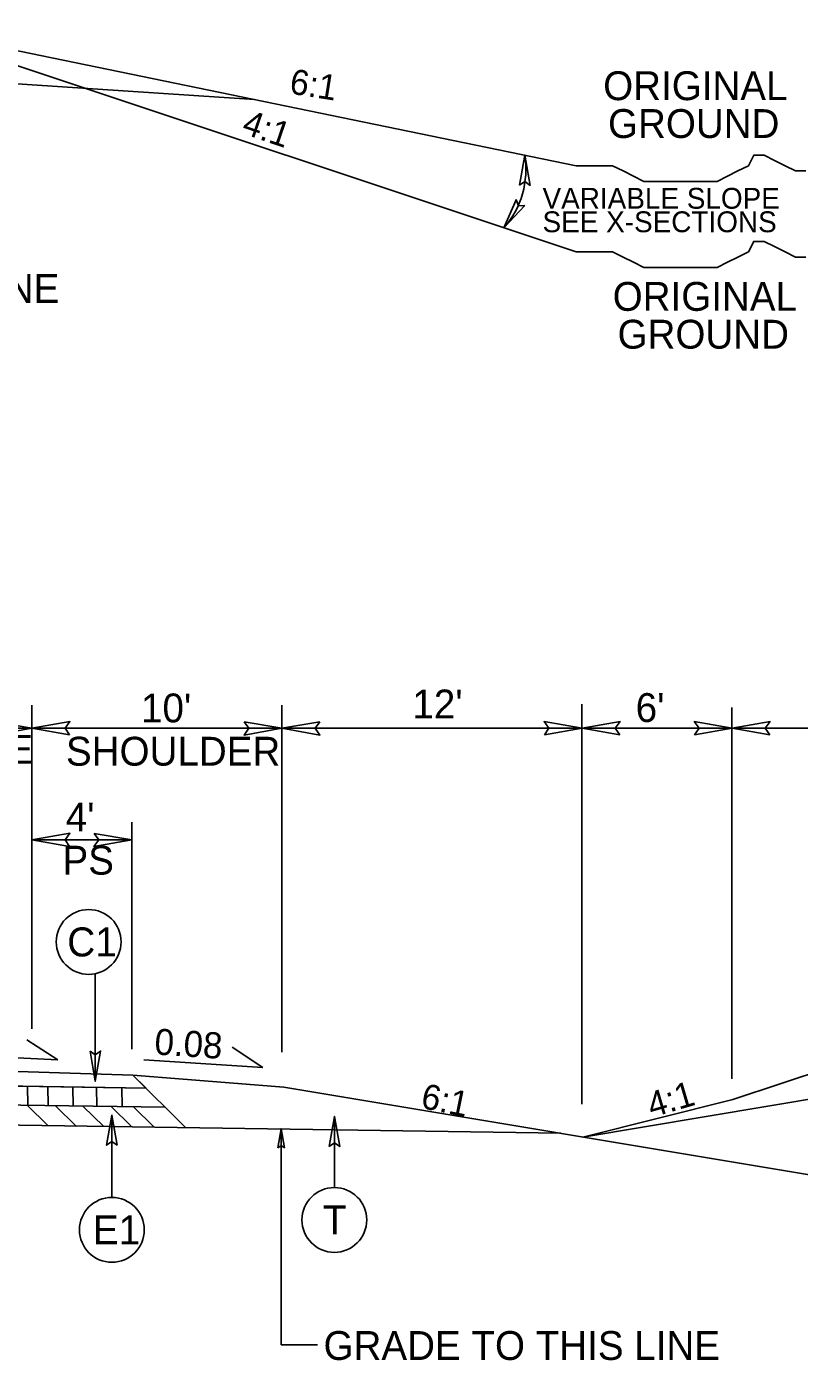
# Model space of a CAD drawing. Extents: x 2176024 to 2177225, y 75947 to 76635.
# Drawn here: x 2176346.9 to 2176377.8, y 76465.6 to 76518.9 of the extents above; entities that cross this region are included whole.
import ezdxf

# ---------------------------------------------------------------- set-up
doc = ezdxf.new("R2010")
doc.units = 0
for name, color, linetype in [('Old_Level_1', 7, 'Continuous'), ('Old_Level_11', 7, 'Continuous'), ('Prop Dimension', 7, 'Continuous'), ('Typical Curb CELL', 7, 'Continuous'), ('Typical Hinge Slope Arterial CELL', 7, 'Continuous'), ('Typical Pavement Slope CELL', 7, 'Continuous'), ('Typical Pavement Slope Information CELL', 7, 'Continuous'), ('Typical Shoulder Slope CELL', 7, 'Continuous'), ('Typical Slope Point Local CELL', 7, 'Continuous'), ('Typical Terminator CELL', 7, 'Continuous'), ('Typical Text General CELL', 7, 'Continuous')]:
    doc.layers.add(name, color=color, linetype=linetype)

msp = doc.modelspace()

# ---------------------------------------------------------------- linework, layer by layer
at = {"layer": 'Old_Level_1'}
for p, q in [((2176346.958, 76475.756), (2176346.947, 76476.512)), ((2176347.771, 76475.744), (2176347.76, 76476.5)), ((2176348.769, 76475.723), (2176348.758, 76476.485)), ((2176349.709, 76475.715), (2176349.698, 76476.471)), ((2176350.727, 76475.7), (2176350.716, 76476.456)), ((2176347.758, 76474.944), (2176346.931, 76475.754)), ((2176348.898, 76474.911), (2176348.063, 76475.73)), ((2176349.989, 76474.903), (2176349.153, 76475.721)), ((2176351.108, 76474.899), (2176350.272, 76475.717)), ((2176352.001, 76474.88), (2176351.174, 76475.69))]:
    msp.add_line(p, q, dxfattribs=at)
at = {"layer": 'Old_Level_11'}
for p, q in [((2176349.651, 76481.016), (2176349.651, 76476.714)), ((2176350.314, 76472.07), (2176350.314, 76475.365)), ((2176359.21, 76472.467), (2176359.21, 76475.309))]:
    msp.add_line(p, q, dxfattribs=at)
for points in [[(2176366.616, 76512.535), (2176366.823, 76513.735), (2176367.036, 76512.528), (2176366.823, 76512.682)], [(2176366.826, 76511.719), (2176365.99, 76510.833), (2176366.479, 76511.957), (2176366.572, 76511.711)], [(2176349.444, 76477.914), (2176349.651, 76476.714), (2176349.864, 76477.92), (2176349.651, 76477.767)], [(2176350.521, 76474.165), (2176350.314, 76475.365), (2176350.101, 76474.159), (2176350.314, 76474.312)], [(2176359.003, 76474.109), (2176359.21, 76475.309), (2176359.423, 76474.103), (2176359.21, 76474.256)]]:
    msp.add_lwpolyline(points, close=True, dxfattribs=at)
for centre in [(2176349.386, 76482.285), (2176359.21, 76471.171), (2176350.314, 76470.774)]:
    msp.add_circle(centre, 1.296, dxfattribs=at)
at = {"layer": 'Prop Dimension'}
for p, q in [((2176347.116, 76478.812), (2176347.116, 76491.752)), ((2176357.116, 76477.884), (2176357.116, 76491.752)), ((2176369.103, 76475.797), (2176369.103, 76491.79)), ((2176375.103, 76476.815), (2176375.103, 76491.656)), ((2176347.116, 76490.824), (2176335.116, 76490.824)), ((2176357.116, 76490.824), (2176347.116, 76490.824)), ((2176357.116, 76490.824), (2176369.116, 76490.824)), ((2176369.116, 76490.824), (2176375.116, 76490.824)), ((2176375.116, 76490.824), (2176385.116, 76490.824)), ((2176351.116, 76477.998), (2176351.116, 76487.074)), ((2176351.116, 76486.364), (2176347.116, 76486.364)), ((2176357.077, 76474.814), (2176357.077, 76466.179)), ((2176358.531, 76466.179), (2176357.077, 76466.179))]:
    msp.add_line(p, q, dxfattribs=at)
at = {"layer": 'Typical Curb CELL'}
msp.add_line((2176368.26, 76474.633), (2176343.298, 76475.004), dxfattribs=at)
at = {"layer": 'Typical Hinge Slope Arterial CELL'}
msp.add_arc((2176363.337, 76513.166), 3.532, 318.6696, 9.272, dxfattribs=at)
at = {"layer": 'Typical Pavement Slope CELL'}
for p, q in [((2176368.874, 76513.313), (2176341.866, 76518.875)), ((2176329.886, 76517.675), (2176356.018, 76515.96)), ((2176369.145, 76474.486), (2176385.145, 76477.152)), ((2176351.157, 76476.96), (2176353.274, 76474.856)), ((2176343.298, 76476.566), (2176351.679, 76476.441)), ((2176385.145, 76471.819), (2176357.193, 76476.478)), ((2176343.298, 76475.811), (2176352.451, 76475.675))]:
    msp.add_line(p, q, dxfattribs=at)
at = {"layer": 'Typical Pavement Slope Information CELL'}
for p, q in [((2176348.153, 76477.572), (2176346.912, 76478.368)), ((2176348.153, 76477.572), (2176340.654, 76477.922)), ((2176356.344, 76477.262), (2176355.119, 76478.082)), ((2176356.344, 76477.262), (2176351.598, 76477.576))]:
    msp.add_line(p, q, dxfattribs=at)
at = {"layer": 'Typical Shoulder Slope CELL'}
for p, q in [((2176368.874, 76509.872), (2176341.866, 76518.875)), ((2176375.145, 76475.986), (2176385.145, 76479.319)), ((2176351.157, 76476.96), (2176357.193, 76476.478)), ((2176369.145, 76474.486), (2176375.145, 76475.986))]:
    msp.add_line(p, q, dxfattribs=at)
at = {"layer": 'Typical Slope Point Local CELL'}
for p, q in [((2176326.441, 76477.731), (2176351.157, 76476.96)), ((2176351.157, 76476.96), (2176343.298, 76477.206)), ((2176351.679, 76476.441), (2176351.157, 76476.96))]:
    msp.add_line(p, q, dxfattribs=at)
for points in [[(2176378.064, 76513.105), (2176377.646, 76513.105), (2176377.229, 76513.313), (2176376.811, 76513.522), (2176376.393, 76513.732), (2176375.976, 76513.732), (2176375.766, 76513.313), (2176375.348, 76513.105), (2176374.931, 76512.895), (2176374.513, 76512.687), (2176374.095, 76512.687), (2176373.678, 76512.687), (2176373.26, 76512.687), (2176372.842, 76512.687), (2176372.425, 76512.687), (2176372.007, 76512.687), (2176371.59, 76512.687), (2176371.172, 76512.895), (2176370.754, 76513.105), (2176370.337, 76513.313), (2176369.709, 76513.313), (2176369.292, 76513.313), (2176368.874, 76513.313)], [(2176378.064, 76509.664), (2176377.646, 76509.664), (2176377.229, 76509.872), (2176376.811, 76510.082), (2176376.393, 76510.291), (2176375.976, 76510.291), (2176375.766, 76509.872), (2176375.348, 76509.664), (2176374.931, 76509.454), (2176374.513, 76509.246), (2176374.095, 76509.246), (2176373.678, 76509.246), (2176373.26, 76509.246), (2176372.842, 76509.246), (2176372.425, 76509.246), (2176372.007, 76509.246), (2176371.59, 76509.246), (2176371.172, 76509.454), (2176370.754, 76509.664), (2176370.337, 76509.872), (2176369.709, 76509.872), (2176369.292, 76509.872), (2176368.874, 76509.872)], [(2176343.298, 76476.566), (2176343.991, 76476.556), (2176344.988, 76476.541), (2176345.929, 76476.527), (2176351.679, 76476.441)]]:
    msp.add_lwpolyline(points, dxfattribs=at)
at = {"layer": 'Typical Terminator CELL'}
for points in [[(2176345.606, 76491.084), (2176347.116, 76490.824), (2176345.598, 76490.556), (2176345.791, 76490.824)], [(2176348.626, 76490.564), (2176347.116, 76490.824), (2176348.634, 76491.093), (2176348.441, 76490.824)], [(2176355.606, 76491.084), (2176357.116, 76490.824), (2176355.598, 76490.556), (2176355.791, 76490.824)], [(2176358.626, 76491.084), (2176357.116, 76490.824), (2176358.634, 76490.556), (2176358.441, 76490.824)], [(2176367.606, 76490.564), (2176369.116, 76490.824), (2176367.598, 76491.093), (2176367.791, 76490.824)], [(2176370.626, 76490.564), (2176369.116, 76490.824), (2176370.634, 76491.093), (2176370.441, 76490.824)], [(2176373.606, 76490.564), (2176375.116, 76490.824), (2176373.598, 76491.093), (2176373.791, 76490.824)], [(2176376.626, 76490.564), (2176375.116, 76490.824), (2176376.634, 76491.093), (2176376.441, 76490.824)], [(2176348.626, 76486.104), (2176347.116, 76486.364), (2176348.634, 76486.632), (2176348.441, 76486.364)], [(2176349.606, 76486.624), (2176351.116, 76486.364), (2176349.598, 76486.096), (2176349.791, 76486.364)], [(2176356.947, 76474.059), (2176357.077, 76474.814), (2176357.211, 76474.055), (2176357.077, 76474.152)]]:
    msp.add_lwpolyline(points, close=True, dxfattribs=at)

# ---------------------------------------------------------------- texts
at = {"layer": 'Old_Level_11'}
for s, p in [('C1', (2176348.529, 76481.705)), ('E1', (2176349.55, 76470.194)), ('T', (2176358.753, 76470.591))]:
    msp.add_text(s, height=1.16, rotation=359.9997, dxfattribs=at).set_placement(p)
at = {"layer": 'Typical Hinge Slope Arterial CELL'}
for s, p in [('VARIABLE SLOPE', (2176367.534, 76511.596)), ('SEE X-SECTIONS', (2176367.534, 76510.657))]:
    msp.add_text(s, height=0.83438, dxfattribs=at).set_placement(p)
at = {"layer": 'Typical Pavement Slope Information CELL'}
msp.add_text('0.08', height=1.0429, rotation=356.2199, dxfattribs=at).set_placement((2176351.994, 76477.787))
at = {"layer": 'Typical Slope Point Local CELL'}
for s, rotation, p in [('6:1', 351.0418, (2176357.38, 76516.208)), ('4:1', 341.041, (2176355.464, 76514.627)), ('6:1', 348.5135, (2176362.626, 76475.654)), ('4:1', 16.4649, (2176371.901, 76475.253))]:
    msp.add_text(s, height=1.0064, rotation=rotation, dxfattribs=at).set_placement(p)
at = {"layer": 'Typical Text General CELL'}
for s, height, p in [('ORIGINAL ', 1.1533, (2176369.958, 76515.937)), ('GROUND', 1.1533, (2176370.152, 76514.425)), ('GRADE TO THIS LINE', 1.15334, (2176332.358, 76507.833)), ('ORIGINAL ', 1.1533, (2176370.339, 76507.515)), ('GROUND', 1.1533, (2176370.533, 76506.003)), ("10' ", 1.1533, (2176351.48, 76491.062)), ("12' ", 1.1533, (2176362.33, 76491.22)), ("6'", 1.1533, (2176371.258, 76491.077)), ('TRAVEL LANE', 1.15334, (2176336.707, 76489.41)), ('SHOULDER', 1.1533, (2176348.479, 76489.332)), ("4' ", 1.1533, (2176348.468, 76486.705)), ('PS', 1.1533, (2176348.339, 76484.975)), ('GRADE TO THIS LINE', 1.15334, (2176358.777, 76465.574))]:
    msp.add_text(s, height=height, dxfattribs=at).set_placement(p)

doc.saveas('drawing.dxf')
